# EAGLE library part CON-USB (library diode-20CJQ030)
Various USB Typ-A Connectors. From: Assmann Electronics Mill-Max Kycon
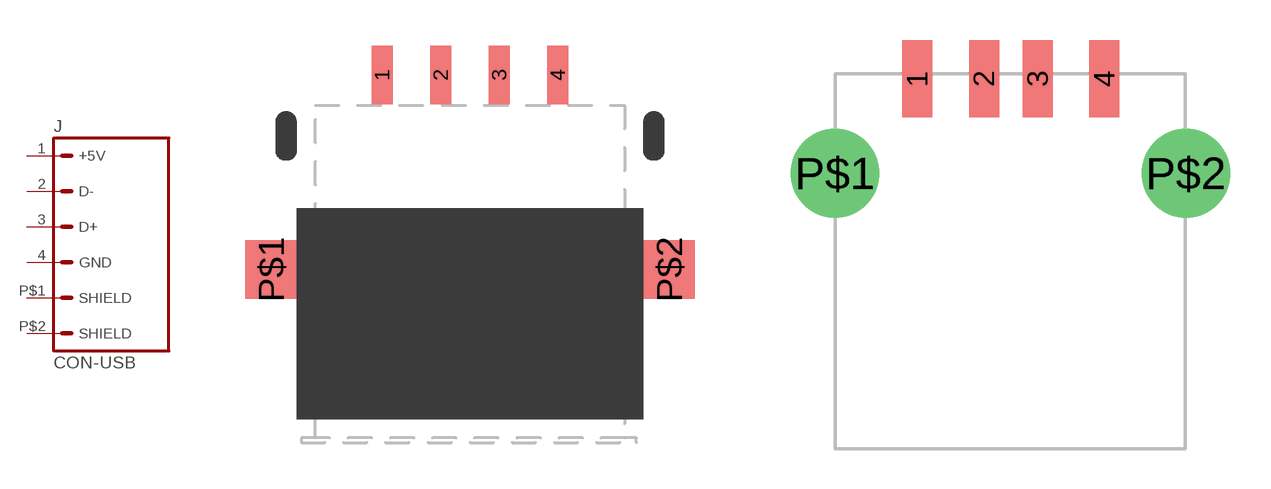
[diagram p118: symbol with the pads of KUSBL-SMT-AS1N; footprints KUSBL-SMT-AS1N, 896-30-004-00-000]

Designator prefix J

## CON-USB-2  [KUSBL-SMT-AS1N]
1  +5V  pas
2  D-  pas
3  D+  pas
4  GND  pas
P$1  SHIELD  pas
P$2  SHIELD  pas

## CON-USB-1  [896-30-004-00-000]
Pads as for KUSBL-SMT-AS1N

## CON-USB-3  [A-USB-A/SMT]
Pads as for KUSBL-SMT-AS1N

## Footprint KUSBL-SMT-AS1N (pad centres in mm)
Kycon KUSBL-SMT-AS1N KUSBL-SMT Series Low Profile A-Type Universal Serial Bus Features: Compatible With Many Computer Peripherals CSA/NRTL Certifed File No. LR78160 Supports Hot Plugging Meets USB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
smd 0.9 x 2.5: 1 -3.75,14.7; 2 -1.25,14.7; 3 1.25,14.7; 4 3.75,14.7
smd 2.2 x 2.5: P$1 -8.5,6.4; P$2 8.5,6.4

## Footprint 896-30-004-00-000 (pad centres in mm)
Mill-MAX's 896 and 897 Series Universal Serial Bus Sockets Features: USB receptacles for thru-hole & surface mount. Plug retention tabs. Kinked locating legs for secure PCB retention. Fully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
smd 1.118 x 2.87: 1 3.073,3.531; 2 5.563,3.531; 3 7.569,3.531; 4 10.058,3.531
drill 2.3 round: P$1 0,0; P$2 13.1,0

## Footprint A-USB-A/SMT (pad centres in mm)
Assmann USB, version A + B , angled, SMD Please send any comments to: messi@users.sourceforge.net
smd 0.9 x 3: 1 -3.5,16; 2 -1,16; 3 1,16; 4 3.5,16
drill 2.3 round: P$1 -6.55,10.3; P$2 6.55,10.3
